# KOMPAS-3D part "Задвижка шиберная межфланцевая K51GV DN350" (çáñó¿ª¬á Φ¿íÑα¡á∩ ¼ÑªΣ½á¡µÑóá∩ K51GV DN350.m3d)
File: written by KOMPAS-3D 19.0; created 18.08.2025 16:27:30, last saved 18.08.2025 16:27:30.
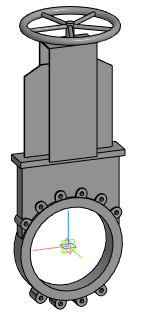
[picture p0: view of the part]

Document properties: Автор: Евгений; Полное имя файла: E:\Dendor Работа Сачек\3D для проектировщиков\2.4 Тип K51GV. Задвижка шиберная межфланцевая\stp_Задвижка шиберная K51GV DN50-400 с маховиком\Задвижка шиберная межфланцевая K51GV DN350.m3d

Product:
- Part/product: Задвижка шиберная межфланцевая K51GV DN350

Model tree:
1. Операция без истории:1  (labels: Задвижка шиберная межфланцевая K51GV DN350)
